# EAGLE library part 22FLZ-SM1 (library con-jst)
CONNECTOR
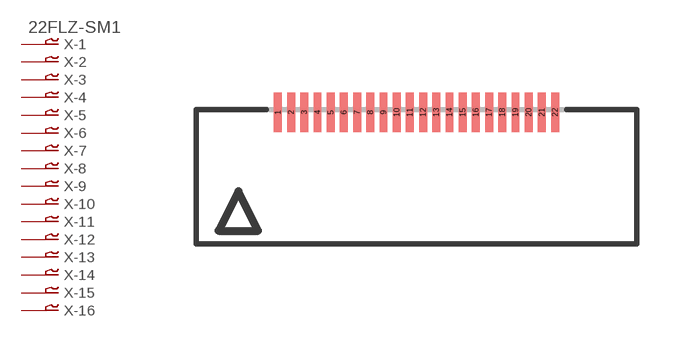
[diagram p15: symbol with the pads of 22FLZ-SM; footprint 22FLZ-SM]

Designator prefix X; gates -1=P-VN -2=P-N -3=P-N -4=P-N -5=P-N -6=P-N -7=P-N -8=P-N -9=P-N -10=P-N -11=P-N -12=P-N -13=P-N -14=P-N -15=P-N -16=P-N -17=P-N -18=P-N -19=P-N -20=P-N -21=P-N -22=P-N

## 22FLZ-SM1 (OC_FARNELL: unknown; OC_NEWARK: unknown)  [22FLZ-SM]
1  -1:1  pas
2  -2:1  pas
3  -3:1  pas
4  -4:1  pas
5  -5:1  pas
6  -6:1  pas
7  -7:1  pas
8  -8:1  pas
9  -9:1  pas
10  -10:1  pas
11  -11:1  pas
12  -12:1  pas
13  -13:1  pas
14  -14:1  pas
15  -15:1  pas
16  -16:1  pas
17  -17:1  pas
18  -18:1  pas
19  -19:1  pas
20  -20:1  pas
21  -21:1  pas
22  -22:1  pas

## Footprint 22FLZ-SM (pad centres in mm)
CONNECTOR
smd 0.3 x 1.5: 1 -5.25,2.5; 2 -4.75,2.5; 3 -4.25,2.5; 4 -3.75,2.5; 5 -3.25,2.5; 6 -2.75,2.5; 7 -2.25,2.5; 8 -1.75,2.5; 9 -1.25,2.5; 10 -0.75,2.5; 11 -0.25,2.5; 12 0.25,2.5; 13 0.75,2.5; 14 1.25,2.5; 15 1.75,2.5; 16 2.25,2.5; 17 2.75,2.5; 18 3.25,2.5; 19 3.75,2.5; 20 4.25,2.5; 21 4.75,2.5; 22 5.25,2.5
